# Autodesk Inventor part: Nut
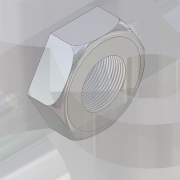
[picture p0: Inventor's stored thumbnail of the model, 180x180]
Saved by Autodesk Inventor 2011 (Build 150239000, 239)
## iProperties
Shininess: 77.0
Length Units: 11269
Angle Units: 11279
Time Units: 11290
Mass Units: 11283
Length Display Precision: 3
Angle Display Precision: 2
Created: 2002-01
Part Number: Nut
Document SubType Name: Modeling
Designer: ***
Density: 1 g/cm^3
Density: 0.0
Volumn: 0.0
Area: 0.0
PropertySet Name: Model Information
Control State: 0
Master: False
Checked Out: False
Author: ***
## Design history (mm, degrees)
sketch "Sketch1"
  geometry: C1 r 40 at (0, 0); C2 r 18.75 at (0, 0)
  constraints: 2 centre point, 1 coincident
  dimensions: "d0" = 37.5 diameter of C2; "d1" = 80 diameter of C1
extrude "Extrusion1" new body sketch "Sketch1" distance "d2" = 25; taper "d3" = 0 deg
fillet "Fillet1" dims "d4" = 9
sketch "Sketch2"
  geometry: L1 (40, 0)-(20, -34.641); L2 (20, -34.641)-(-20, -34.641); L3 (-20, -34.641)-(-40, 0); L4 (-40, 0)-(-20, 34.641); L5 (-20, 34.641)-(20, 34.641); L6 (20, 34.641)-(40, 0); C1 r 31 at (0, 0) reference; 1 further point
  constraints: 12 end point, 1 coincident, 11 other
extrude "Extrusion2" sketch "Sketch2" stored distance "d5" = 25; taper "d6" = 0 deg
thread "Thread1" dims "d7" = 10, "d8" = 0
body "Solid1"
